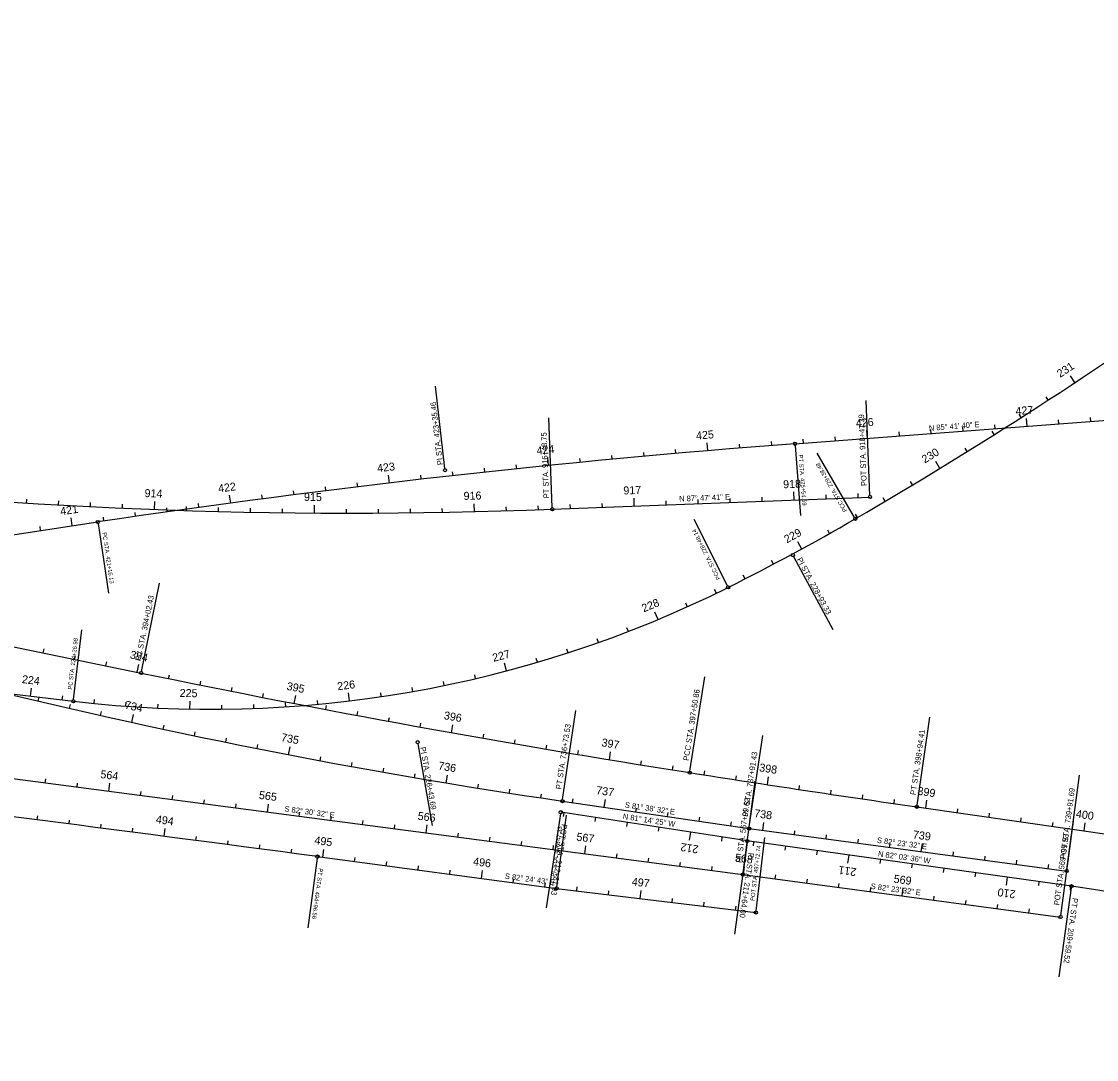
# Model space of a CAD drawing. Extents: x 919452 to 931278, y 583254 to 665650.
# Drawn here: x 927714 to 928386, y 636383 to 637032 of the extents above; entities that cross this region are included whole.
import ezdxf

# ---------------------------------------------------------------- set-up
doc = ezdxf.new("R2010")
doc.units = 0
for name, color, linetype in [('CLConst_dp', 7, 'Continuous'), ('CurveDataLabel_dp', 7, 'Continuous'), ('StationTicL_dp', 7, 'Continuous'), ('StationTicS_dp', 7, 'Continuous'), ('TextBLStation', 7, 'Continuous'), ('TextLabel', 7, 'Continuous')]:
    doc.layers.add(name, color=color, linetype=linetype)

msp = doc.modelspace()

# ---------------------------------------------------------------- linework, layer by layer
at = {"layer": 'CLConst_dp'}
for p, q in [((928197.18, 636767.96), (928404.75, 636783.58)), ((928045.6, 636727.06), (928244.09, 636734.7)), ((927642.87, 636701.38), (927761.55, 636719.1)), ((927592.72, 636665.12), (927788.61, 636624.75)), ((927568.79, 636628.21), (927746.27, 636607.13)), ((927630.5, 636569.05), (928164.62, 636498.82)), ((928051.87, 636544.69), (928168.51, 636527.56)), ((928167.41, 636519.81), (928050.85, 636537.77)), ((928273.35, 636541.15), (929358.98, 636384.96)), ((928168.51, 636527.56), (928367, 636501.04)), ((928369.93, 636491.56), (928167.41, 636519.81)), ((927898.78, 636510.08), (928048.23, 636490.17)), ((928164.62, 636498.82), (928363.16, 636472.3)), ((928048.23, 636490.17), (928172.73, 636475.11))]:
    msp.add_line(p, q, dxfattribs=at)
for centre, radius, start, end in [((926819.39, 639157.21), 2817.49, 300.15904, 311.0304), ((928647.64, 630784.89), 6000, 94.305602, 98.492547), ((927919.83, 639992.88), 3268.24, 263.18963, 272.20538), ((927524.56, 637943.61), 1413.9, 296.49836, 300.15904), ((927831.84, 637327.26), 725.2, 263.22367, 296.49836), ((929274.27, 643833.25), 7360, 258.354474, 261.066917), ((928618.75, 640403.27), 3900, 255.98637, 261.64217), ((922956.96, 599413.81), 37423.99, 82.411957, 83.554939), ((929843.22, 647452.8), 11024, 261.066917, 261.81299), ((928270.99, 635782.23), 716.2, 0.06217, 82.06007)]:
    msp.add_arc(centre, radius, start, end, dxfattribs=at)
at = {"layer": 'CurveDataLabel_dp'}
for p, q in [((927978.36, 636752.48), (927972.59, 636803.92)), ((928244.05, 636735.7), (928241.77, 636795.02)), ((928045.56, 636728.06), (928043.4, 636784.24)), ((928197.25, 636766.96), (928200.55, 636723.2)), ((928234.4, 636721.97), (928211.07, 636762.13)), ((927761.7, 636718.11), (927768.2, 636674.58)), ((928154.96, 636679.14), (928134.27, 636720.63)), ((928196.31, 636697.52), (928220.91, 636651.9)), ((927788.81, 636625.73), (927800.18, 636680.92)), ((927746.39, 636608.12), (927751.58, 636651.81)), ((928131.56, 636563.51), (928140.8, 636622.34)), ((928052.01, 636545.68), (928060.19, 636601.34)), ((928273.49, 636542.14), (928281.41, 636597.2)), ((928168.66, 636528.55), (928177.06, 636585.72)), ((927961.63, 636580.57), (927970.5, 636529.58)), ((928164.75, 636499.81), (928172.28, 636557.1)), ((928367.14, 636502.04), (928375, 636560.88)), ((928050.7, 636536.78), (928041.65, 636478.03)), ((928048.36, 636491.17), (928054.32, 636535.86)), ((928363.3, 636473.29), (928371.17, 636532.21)), ((928172.85, 636476.1), (928178.41, 636521.99)), ((928167.27, 636518.82), (928159.3, 636461.67)), ((927898.65, 636509.09), (927892.86, 636465.59)), ((928369.79, 636490.57), (928362.02, 636434.86))]:
    msp.add_line(p, q, dxfattribs=at)
for centre in [(928197.18, 636767.96), (927978.47, 636751.49), (928244.09, 636734.7), (928045.6, 636727.06), (927761.55, 636719.1), (928234.91, 636721.1), (928195.84, 636698.4), (928155.4, 636678.24), (927788.61, 636624.75), (927746.27, 636607.13), (927961.46, 636581.56), (928131.4, 636562.52), (928051.87, 636544.69), (928273.35, 636541.15), (928050.85, 636537.77), (928168.51, 636527.56), (928167.41, 636519.81), (927898.78, 636510.08), (928367, 636501.04), (928164.62, 636498.82), (928048.23, 636490.17), (928369.93, 636491.56), (928172.73, 636475.11), (928363.16, 636472.3)]:
    msp.add_circle(centre, 1, dxfattribs=at)
at = {"layer": 'StationTicL_dp'}
for p, q in [((928372.16, 636806.21), (928369.41, 636810.38)), ((928342.18, 636778.87), (928341.81, 636783.86)), ((928242.46, 636771.37), (928242.09, 636776.35)), ((928142.77, 636763.61), (928142.35, 636768.59)), ((928043.2, 636754.37), (928042.69, 636759.34)), ((928287.76, 636752.59), (928285.15, 636756.86)), ((927943.79, 636743.46), (927943.21, 636748.43)), ((928196.74, 636732.88), (928196.54, 636737.87)), ((927796.91, 636726.95), (927797.1, 636731.95)), ((927844.59, 636730.91), (927843.92, 636735.86)), ((927996.87, 636725.54), (927996.76, 636730.54)), ((928096.81, 636729.03), (928096.62, 636734.03)), ((927896.88, 636724.72), (927896.92, 636729.72)), ((927745.6, 636716.72), (927744.86, 636721.66)), ((928201.38, 636702.23), (928198.98, 636706.62)), ((928111.64, 636658.21), (928109.71, 636662.82)), ((927786.23, 636625.24), (927787.24, 636630.14)), ((928017.01, 636626.1), (928015.74, 636630.93)), ((927719.48, 636610.31), (927720.07, 636615.28)), ((927884.3, 636605.69), (927885.24, 636610.6)), ((927918.88, 636607.3), (927918.28, 636612.27)), ((927819.09, 636602.17), (927819.18, 636607.17)), ((927782.85, 636593.91), (927783.93, 636598.79)), ((927982.62, 636587.47), (927983.5, 636592.39)), ((927880.79, 636573.73), (927881.74, 636578.64)), ((928081.19, 636570.59), (928082, 636575.53)), ((927768.41, 636550.92), (927769.06, 636555.88)), ((927979.22, 636556.07), (927980.04, 636561)), ((928179.96, 636555), (928180.72, 636559.94)), ((927867.56, 636537.88), (927868.21, 636542.84)), ((928078.05, 636540.85), (928078.78, 636545.79)), ((928278.89, 636540.36), (928279.6, 636545.31)), ((927966.7, 636524.84), (927967.36, 636529.8)), ((928177.01, 636526.42), (928177.67, 636531.38)), ((928377.87, 636526.12), (928378.58, 636531.07)), ((927803.05, 636522.71), (927803.7, 636527.67)), ((928131.83, 636525.29), (928131.07, 636520.35)), ((928065.85, 636511.81), (928066.5, 636516.76)), ((928276.13, 636513.18), (928276.79, 636518.14)), ((927902.19, 636509.63), (927902.85, 636514.59)), ((928230.79, 636510.97), (928230.1, 636506.01)), ((928165, 636498.77), (928165.66, 636503.72)), ((928001.31, 636496.43), (928001.98, 636501.38)), ((928329.84, 636497.15), (928329.15, 636492.2)), ((928100.52, 636483.85), (928101.12, 636488.81)), ((928264.12, 636485.53), (928264.78, 636490.49))]:
    msp.add_line(p, q, dxfattribs=at)
at = {"layer": 'StationTicS_dp'}
for p, q in [((928355.43, 636795.25), (928354.07, 636797.34)), ((928338.63, 636784.4), (928337.28, 636786.51)), ((928382.07, 636781.88), (928381.88, 636784.37)), ((928302.3, 636775.87), (928302.11, 636778.36)), ((928322.24, 636777.37), (928322.05, 636779.87)), ((928362.13, 636780.38), (928361.94, 636782.87)), ((928202.58, 636768.36), (928202.39, 636770.86)), ((928222.52, 636769.86), (928222.33, 636772.36)), ((928262.41, 636772.87), (928262.22, 636775.36)), ((928282.35, 636774.37), (928282.16, 636776.86)), ((928321.75, 636773.68), (928320.41, 636775.79)), ((928122.84, 636761.89), (928122.62, 636764.39)), ((928162.7, 636765.26), (928162.5, 636767.75)), ((928182.64, 636766.84), (928182.44, 636769.34)), ((928304.79, 636763.07), (928303.47, 636765.2)), ((928063.1, 636756.35), (928062.85, 636758.84)), ((928083.01, 636758.26), (928082.77, 636760.75)), ((928102.92, 636760.11), (928102.69, 636762.6)), ((927983.53, 636748.02), (927983.26, 636750.51)), ((928003.41, 636750.2), (928003.14, 636752.69)), ((928023.3, 636752.32), (928023.04, 636754.81)), ((927923.94, 636741.08), (927923.63, 636743.57)), ((927963.66, 636745.78), (927963.37, 636748.26)), ((928270.65, 636742.23), (928269.36, 636744.37)), ((927884.24, 636736.13), (927883.93, 636738.61)), ((927904.09, 636738.64), (927903.78, 636741.12)), ((928236.71, 636734.42), (928236.61, 636736.91)), ((927717.01, 636730.94), (927717.17, 636733.43)), ((927736.98, 636729.76), (927737.12, 636732.25)), ((927756.95, 636728.7), (927757.07, 636731.19)), ((927776.93, 636727.76), (927777.04, 636730.26)), ((927824.77, 636728.2), (927824.43, 636730.67)), ((927864.41, 636733.55), (927864.08, 636736.03)), ((928056.84, 636727.49), (928056.74, 636729.99)), ((928076.83, 636728.26), (928076.73, 636730.76)), ((928116.8, 636729.8), (928116.7, 636732.3)), ((928136.78, 636730.57), (928136.69, 636733.07)), ((928156.77, 636731.34), (928156.67, 636733.84)), ((928176.75, 636732.11), (928176.66, 636734.61)), ((928216.72, 636733.65), (928216.63, 636736.14)), ((928253.47, 636731.99), (928252.2, 636734.14)), ((927785.17, 636722.58), (927784.81, 636725.05)), ((927804.96, 636725.42), (927804.61, 636727.9)), ((927816.9, 636726.26), (927816.98, 636728.76)), ((927836.89, 636725.69), (927836.95, 636728.19)), ((927856.88, 636725.24), (927856.93, 636727.74)), ((927876.88, 636724.92), (927876.91, 636727.42)), ((927916.88, 636724.64), (927916.88, 636727.14)), ((927936.88, 636724.68), (927936.87, 636727.18)), ((927956.88, 636724.85), (927956.85, 636727.35)), ((927976.88, 636725.13), (927976.83, 636727.63)), ((928016.87, 636726.08), (928016.79, 636728.58)), ((928036.86, 636726.73), (928036.77, 636729.23)), ((928236.22, 636721.87), (928234.96, 636724.03)), ((927765.38, 636719.67), (927765.01, 636722.14)), ((927725.82, 636713.76), (927725.45, 636716.24)), ((928218.87, 636711.92), (928217.64, 636714.1)), ((928183.75, 636692.78), (928182.58, 636694.99)), ((928165.99, 636683.58), (928164.86, 636685.81)), ((928148.09, 636674.65), (928147, 636676.9)), ((928129.98, 636666.18), (928128.95, 636668.46)), ((928093.08, 636650.75), (928092.18, 636653.08)), ((928074.33, 636643.8), (928073.49, 636646.16)), ((927727.46, 636637.35), (927727.97, 636639.8)), ((928055.39, 636637.37), (928054.62, 636639.75)), ((927747.05, 636633.32), (927747.56, 636635.76)), ((927766.64, 636629.28), (927767.14, 636631.73)), ((928036.28, 636631.47), (928035.57, 636633.87)), ((927805.82, 636621.23), (927806.32, 636623.67)), ((927997.61, 636621.26), (927997.04, 636623.69)), ((927825.42, 636617.26), (927825.92, 636619.71)), ((927845.04, 636613.35), (927845.52, 636615.8)), ((927978.08, 636616.96), (927977.57, 636619.41)), ((927724.35, 636607.22), (927724.92, 636609.65)), ((927739.34, 636607.95), (927739.63, 636610.43)), ((927864.66, 636609.49), (927865.14, 636611.95)), ((927938.7, 636609.98), (927938.33, 636612.45)), ((927958.44, 636613.2), (927958, 636615.66)), ((927743.83, 636602.68), (927744.39, 636605.12)), ((927759.21, 636605.71), (927759.46, 636608.19)), ((927779.13, 636603.98), (927779.32, 636606.47)), ((927799.1, 636602.8), (927799.21, 636605.3)), ((927839.09, 636602.1), (927839.06, 636604.6)), ((927859.08, 636602.57), (927858.99, 636605.07)), ((927879.05, 636603.6), (927878.89, 636606.09)), ((927898.99, 636605.18), (927898.76, 636607.66)), ((927903.94, 636601.94), (927904.41, 636604.4)), ((927763.33, 636598.24), (927763.88, 636600.68)), ((927923.6, 636598.24), (927924.06, 636600.7)), ((927943.26, 636594.6), (927943.72, 636597.06)), ((927802.4, 636589.67), (927802.92, 636592.11)), ((927962.94, 636591.01), (927963.38, 636593.47)), ((927821.97, 636585.53), (927822.48, 636587.98)), ((927841.56, 636581.5), (927842.06, 636583.95)), ((928002.32, 636583.99), (928002.75, 636586.45)), ((928022.02, 636580.56), (928022.45, 636583.02)), ((927861.17, 636577.56), (927861.65, 636580.02)), ((928041.73, 636577.18), (928042.15, 636579.65)), ((928061.46, 636573.86), (928061.87, 636576.33)), ((927900.44, 636569.99), (927900.9, 636572.45)), ((927920.11, 636566.36), (927920.56, 636568.82)), ((928100.93, 636567.38), (928101.33, 636569.84)), ((927939.8, 636562.83), (927940.23, 636565.29)), ((928120.68, 636564.22), (928121.07, 636566.68)), ((928140.43, 636561.11), (928140.82, 636563.58)), ((927728.75, 636556.13), (927729.08, 636558.61)), ((927748.58, 636553.53), (927748.91, 636556.01)), ((927959.5, 636559.4), (927959.92, 636561.86)), ((927998.96, 636552.84), (927999.35, 636555.31)), ((928160.2, 636558.03), (928160.58, 636560.5)), ((927788.24, 636548.31), (927788.57, 636550.79)), ((928018.71, 636549.71), (928019.1, 636552.18)), ((928038.48, 636546.68), (928038.85, 636549.16)), ((928199.74, 636552), (928200.11, 636554.47)), ((928219.52, 636549.04), (928219.88, 636551.51)), ((928239.3, 636546.11), (928239.66, 636548.58)), ((927808.07, 636545.7), (927808.4, 636548.18)), ((927827.9, 636543.1), (927828.23, 636545.58)), ((927847.73, 636540.49), (927848.05, 636542.97)), ((928058.27, 636543.75), (928058.63, 636546.23)), ((928259.09, 636543.22), (928259.45, 636545.69)), ((927723.71, 636532.99), (927724.03, 636535.47)), ((927887.39, 636535.27), (927887.71, 636537.75)), ((927907.22, 636532.67), (927907.54, 636535.15)), ((928052.76, 636537.47), (928052.38, 636535)), ((928097.84, 636537.94), (928098.2, 636540.41)), ((928117.63, 636535.03), (928117.99, 636537.51)), ((928298.68, 636537.51), (928299.04, 636539.98)), ((928318.48, 636534.66), (928318.83, 636537.14)), ((927743.55, 636530.43), (927743.87, 636532.91)), ((927763.38, 636527.87), (927763.71, 636530.35)), ((927927.05, 636530.06), (927927.37, 636532.54)), ((927946.88, 636527.45), (927947.2, 636529.93)), ((928072.53, 636534.43), (928072.15, 636531.96)), ((928092.29, 636531.38), (928091.91, 636528.91)), ((928137.42, 636532.12), (928137.78, 636534.6)), ((928157.2, 636529.22), (928157.57, 636531.69)), ((928338.27, 636531.81), (928338.63, 636534.29)), ((928358.07, 636528.97), (928358.43, 636531.44)), ((927783.22, 636525.3), (927783.54, 636527.78)), ((927822.88, 636520.12), (927823.21, 636522.6)), ((927986.53, 636522.24), (927986.86, 636524.72)), ((928006.36, 636519.63), (928006.69, 636522.11)), ((928112.06, 636528.34), (928111.68, 636525.86)), ((928151.59, 636522.24), (928151.21, 636519.77)), ((928196.83, 636523.77), (928197.16, 636526.25)), ((928216.65, 636521.13), (928216.99, 636523.6)), ((927842.71, 636517.51), (927843.04, 636519.99)), ((927862.54, 636514.89), (927862.87, 636517.37)), ((928026.19, 636517.02), (928026.52, 636519.5)), ((928046.02, 636514.41), (928046.35, 636516.89)), ((928171.37, 636519.26), (928171.02, 636516.78)), ((928191.18, 636516.49), (928190.83, 636514.02)), ((928236.48, 636518.48), (928236.81, 636520.96)), ((928256.3, 636515.83), (928256.63, 636518.31)), ((927882.37, 636512.27), (927882.69, 636514.75)), ((927922.02, 636506.99), (927922.35, 636509.47)), ((928085.68, 636509.2), (928086.01, 636511.68)), ((928105.51, 636506.59), (928105.84, 636509.07)), ((928210.99, 636513.73), (928210.64, 636511.25)), ((928295.95, 636510.53), (928296.28, 636513.01)), ((928315.77, 636507.89), (928316.11, 636510.37)), ((927941.84, 636504.35), (927942.17, 636506.83)), ((927961.67, 636501.71), (927962, 636504.19)), ((927981.49, 636499.07), (927981.82, 636501.54)), ((928125.34, 636503.98), (928125.66, 636506.46)), ((928145.17, 636501.38), (928145.49, 636503.86)), ((928250.6, 636508.2), (928250.26, 636505.73)), ((928270.41, 636505.44), (928270.07, 636502.97)), ((928290.22, 636502.68), (928289.87, 636500.2)), ((928335.6, 636505.24), (928335.93, 636507.72)), ((928355.42, 636502.59), (928355.75, 636505.07)), ((928021.14, 636493.78), (928021.47, 636496.26)), ((928184.82, 636496.12), (928185.15, 636498.6)), ((928204.65, 636493.47), (928204.98, 636495.95)), ((928310.03, 636499.92), (928309.68, 636497.44)), ((928040.96, 636491.14), (928041.29, 636493.62)), ((928060.81, 636488.65), (928061.11, 636491.13)), ((928080.66, 636486.25), (928080.96, 636488.73)), ((928224.47, 636490.82), (928224.8, 636493.3)), ((928244.29, 636488.18), (928244.62, 636490.66)), ((928349.64, 636494.39), (928349.3, 636491.91)), ((928369.45, 636491.63), (928369.11, 636489.15)), ((928120.37, 636481.44), (928120.67, 636483.93)), ((928140.23, 636479.04), (928140.53, 636481.52)), ((928283.94, 636482.88), (928284.27, 636485.36)), ((928303.76, 636480.23), (928304.1, 636482.71)), ((928160.08, 636476.64), (928160.38, 636479.12)), ((928323.59, 636477.59), (928323.92, 636480.06)), ((928343.41, 636474.94), (928343.74, 636477.42))]:
    msp.add_line(p, q, dxfattribs=at)

# ---------------------------------------------------------------- texts
at = {"layer": 'CurveDataLabel_dp'}
for s, height, rotation, p in [('PI STA. 423+35.46', 3.5, 96.39907, (927977.21, 636754.87)), ('POT STA. 918+47.39', 3.5, 92.20538, (928242.07, 636741.63)), ('PT STA. 916+48.75', 3.5, 92.20538, (928043.58, 636733.98)), ('PT STA. 425+54.59', 2.625, 274.3056, (928199.45, 636761.11)), ('PCC STA. 229+38.48', 2.625, 120.15904, (928229.88, 636726.28)), ('PC STA. 421+16.13', 2.625, 278.49255, (927764.32, 636712.44)), ('PCC STA. 228+48.14', 2.625, 116.49836, (928150.71, 636683.73)), ('PI STA. 228+93.33', 3.5, 298.3287, (928198.27, 636695.74)), ('PC STA. 394+02.43', 3.5, 78.35447, (927788.31, 636631.96)), ('PC STA. 224+26.98', 2.625, 83.22367, (927745.36, 636614.28)), ('PCC STA. 397+50.86', 3.5, 81.06692, (928130.76, 636569.71)), ('PT STA. 736+73.53', 3.5, 81.64217, (928051.15, 636551.87)), ('PT STA. 398+94.41', 3.5, 81.81299, (928272.61, 636548.33)), ('PI STA. 226+43.69', 3.5, 279.86101, (927962.93, 636578.26)), ('PI  STA. 737+91.43', 3.5, 81.64217, (928167.8, 636534.74)), ('POT STA. 739+91.69', 3.5, 82.39217, (928366.2, 636508.21)), ('PI  STA. 567+99.62', 3.5, 82.50875, (928163.79, 636505.99)), ('POT STA. 212+81.93', 3.5, 261.24036, (928051.51, 636530.58)), ('PI  STA. 496+47.33', 2.625, 82.41196, (928047.42, 636497.34)), ('POT STA. 569+99.93', 3.5, 82.39217, (928362.36, 636479.47)), ('POT STA. 497+72.74', 2.625, 83.09907, (928171.84, 636482.27)), ('PI  STA. 211+64.00', 3.5, 262.06007, (928168.18, 636512.63)), ('PT STA. 494+96.56', 2.625, 262.41196, (927899.59, 636502.91)), ('PT STA. 209+59.52', 3.5, 262.06007, (928370.69, 636484.39))]:
    msp.add_text(s, height=height, rotation=rotation, dxfattribs=at).set_placement(p)
at = {"layer": 'TextBLStation'}
for s, rotation, p in [('231', 33.44367, (928362.91, 636809.09)), ('427', 4.3056, (928335.16, 636785.87)), ('426', 4.3056, (928235.39, 636778.35)), ('425', 4.82686, (928135.59, 636770.53)), ('424', 5.78179, (928035.99, 636761.17)), ('230', 31.4101, (928278.28, 636755.59)), ('423', 6.73672, (927936.37, 636750.14)), ('422', 7.69165, (927837.06, 636737.46)), ('918', 2.20538, (928189.88, 636740.12)), ('914', 357.84449, (927790.71, 636734.69)), ('915', 359.59759, (927890.37, 636732.26)), ('916', 1.3507, (927990.17, 636732.89)), ('917', 2.20538, (928090.05, 636736.27)), ('421', 8.49255, (927738.42, 636723.23)), ('229', 28.59971, (928192.05, 636705.68)), ('228', 22.69458, (928102.68, 636662.59)), ('394', 348.35447, (927781.39, 636633.9)), ('227', 14.79386, (928008.84, 636631.7)), ('224', 353.22367, (927713.92, 636618.52)), ('395', 349.11404, (927879.27, 636614.3)), ('226', 6.89314, (927911.49, 636613.96)), ('225', 358.99243, (927812.66, 636609.79)), ('734', 347.62361, (927778.13, 636602.62)), ('396', 349.89252, (927977.51, 636596)), ('735', 349.09273, (927875.77, 636582.33)), ('397', 350.67099, (928076.02, 636579.04)), ('736', 350.56185, (927974, 636564.54)), ('564', 352.50875, (927762.96, 636559.2)), ('398', 351.32232, (928174.6, 636563.4)), ('565', 352.50875, (927862.03, 636546.17)), ('737', 351.64217, (928072.74, 636549.21)), ('399', 351.81299, (928273.49, 636548.71)), ('494', 352.55979, (927797.59, 636530.99)), ('566', 352.50875, (927961.2, 636533.13)), ('738', 352.39217, (928171.49, 636534.73)), ('400', 351.81299, (928372.48, 636534.47)), ('495', 352.41196, (927896.67, 636517.93)), ('567', 352.50875, (928060.41, 636520.09)), ('739', 352.39217, (928270.64, 636521.48)), ('212', 171.24036, (928137.19, 636516.87)), ('496', 352.41196, (927995.83, 636504.72)), ('568', 352.39217, (928159.48, 636507.07)), ('211', 172.06007, (928235.84, 636502.69)), ('497', 353.09907, (928094.99, 636492.07)), ('569', 352.39217, (928258.63, 636493.83)), ('210', 172.06007, (928335.26, 636488.82))]:
    msp.add_text(s, height=5, rotation=rotation, dxfattribs=at).set_placement(p)
at = {"layer": 'TextLabel'}
for s, rotation, p in [('N 85%%d 41\' 40" E', 4.3056, (928281, 636776.02)), ('N 87%%d 47\' 41" E', 2.20538, (928124.9, 636731.86)), ('S 81%%d 38\' 32" E', 351.64217, (928090.73, 636540.75)), ('S 82%%d 30\' 32" E', 352.50875, (927878.03, 636538.27)), ('N 81%%d 14\' 25" W', 351.24036, (928089.44, 636533.59)), ('S 82%%d 23\' 32" E', 352.39217, (928248.24, 636518.67)), ('N 82%%d 03\' 36" W', 352.06007, (928248.91, 636510.21)), ('S 82%%d 24\' 43" E', 352.41196, (928015.74, 636496.27)), ('S 82%%d 23\' 32" E', 352.39217, (928244.37, 636489.93))]:
    msp.add_text(s, height=3.5, rotation=rotation, dxfattribs=at).set_placement(p)

doc.saveas('drawing.dxf')
